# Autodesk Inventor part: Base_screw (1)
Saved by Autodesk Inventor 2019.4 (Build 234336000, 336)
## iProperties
Created: 2019-10
Part Number: Base_screw (1)
Material: Generic
Document SubType Name: Modeling
Designer: Administrator
Density: 1 g/cm^3
Appearance: Default
Title: Base_screw (1)
Author: Administrator
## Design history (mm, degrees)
feature "Body1"
body "Solid1"
